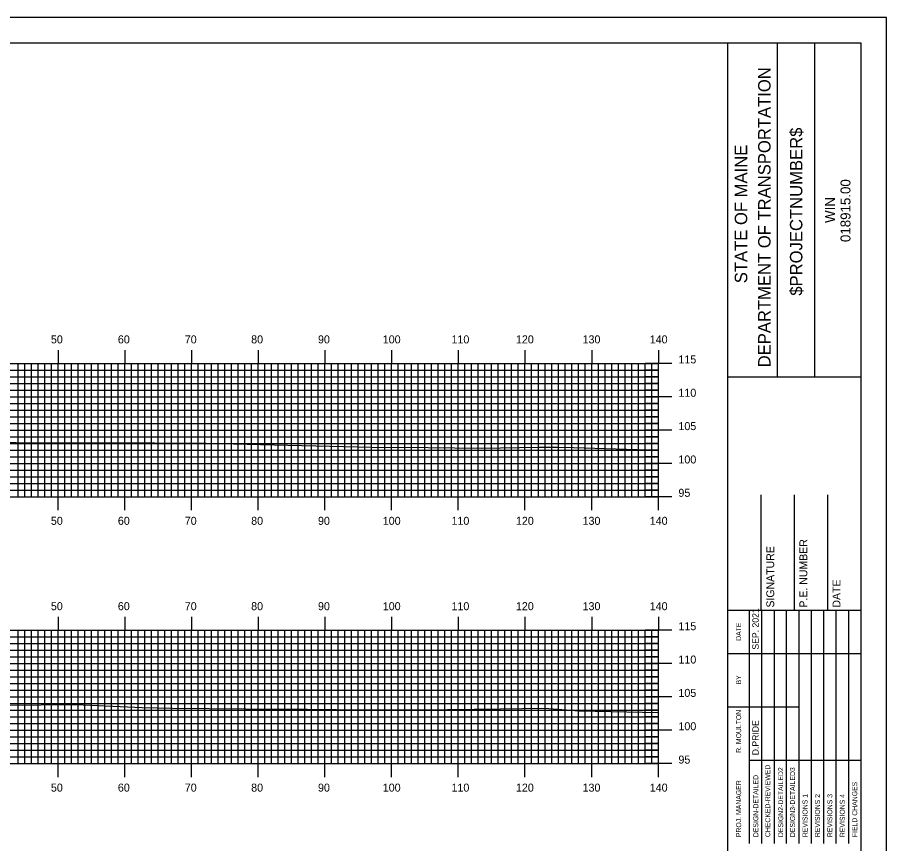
# Model space of a CAD drawing. Extents: x 1773596 to 1773940, y 442591 to 442811.
# Drawn here: x 1773806.1 to 1773936.4, y 442686.7 to 442810.5 of the extents above; entities that cross this region are included whole.
import ezdxf

# ---------------------------------------------------------------- set-up
doc = ezdxf.new("R2010")
doc.units = 0
for name, color, linetype in [('BORDER', 7, 'Continuous'), ('H_V ANNOTATION', 7, 'Continuous'), ('MAJOR', 7, 'Continuous'), ('MINOR', 7, 'Continuous'), ('PLOT BOUNDARY', 7, 'Continuous'), ('S_Roadway_Centerline', 7, 'Continuous')]:
    doc.layers.add(name, color=color, linetype=linetype)

msp = doc.modelspace()

# ---------------------------------------------------------------- linework, layer by layer
at = {"layer": 'BORDER'}
for p, q in [((1773912.55, 442596.67), (1773912.55, 442806.67)), ((1773920, 442756.66), (1773920, 442806.66)), ((1773925.59, 442756.66), (1773925.59, 442806.66)), ((1773912.55, 442756.65), (1773932.55, 442756.65)), ((1773917.55, 442721.67), (1773917.55, 442738.97)), ((1773922.55, 442721.67), (1773922.55, 442738.97)), ((1773927.55, 442721.67), (1773927.55, 442738.97)), ((1773912.55, 442721.67), (1773932.55, 442721.67))]:
    msp.add_line(p, q, dxfattribs=at)
msp.add_lwpolyline([(1773612.55, 442596.67), (1773932.55, 442596.67), (1773932.55, 442806.67), (1773612.55, 442806.67)], close=True, dxfattribs=at)
for points in [[(1773915.78, 442715.17), (1773915.78, 442721.67)], [(1773917.64, 442686.68), (1773917.64, 442721.67)], [(1773919.5, 442721.67), (1773919.5, 442686.68)], [(1773921.37, 442686.68), (1773921.37, 442721.67)], [(1773923.23, 442686.68), (1773923.23, 442721.67)], [(1773925.09, 442686.68), (1773925.09, 442721.67)], [(1773926.96, 442686.68), (1773926.96, 442721.67)], [(1773928.82, 442686.68), (1773928.82, 442721.67)], [(1773930.68, 442686.68), (1773930.68, 442721.67)], [(1773915.78, 442686.68), (1773915.78, 442720.26)], [(1773912.55, 442715.17), (1773932.55, 442715.17)], [(1773912.55, 442707.17), (1773915.78, 442707.17)], [(1773915.78, 442707.17), (1773923.23, 442707.17)], [(1773915.78, 442699.17), (1773932.55, 442699.17)]]:
    msp.add_lwpolyline(points, dxfattribs=at)
at = {"layer": 'MAJOR'}
for p, q in [((1773812.15, 442760.67), (1773812.15, 442758.67)), ((1773822.15, 442760.67), (1773822.15, 442758.67)), ((1773832.15, 442760.67), (1773832.15, 442758.67)), ((1773842.15, 442760.67), (1773842.15, 442758.67)), ((1773852.15, 442760.67), (1773852.15, 442758.67)), ((1773862.15, 442760.67), (1773862.15, 442758.67)), ((1773872.15, 442760.67), (1773872.15, 442758.67)), ((1773882.15, 442760.67), (1773882.15, 442758.67)), ((1773892.15, 442760.67), (1773892.15, 442758.67)), ((1773902.15, 442760.67), (1773902.15, 442758.67)), ((1773622.15, 442758.67), (1773902.15, 442758.67)), ((1773622.15, 442758.67), (1773902.15, 442758.67)), ((1773812.15, 442738.67), (1773812.15, 442758.67)), ((1773822.15, 442738.67), (1773822.15, 442758.67)), ((1773832.15, 442738.67), (1773832.15, 442758.67)), ((1773842.15, 442738.67), (1773842.15, 442758.67)), ((1773852.15, 442738.67), (1773852.15, 442758.67)), ((1773862.15, 442738.67), (1773862.15, 442758.67)), ((1773872.15, 442738.67), (1773872.15, 442758.67)), ((1773882.15, 442738.67), (1773882.15, 442758.67)), ((1773892.15, 442738.67), (1773892.15, 442758.67)), ((1773904.15, 442758.67), (1773900.14, 442758.67)), ((1773902.15, 442738.67), (1773902.15, 442758.67)), ((1773902.15, 442738.67), (1773902.15, 442758.67)), ((1773622.15, 442753.67), (1773902.15, 442753.67)), ((1773904.15, 442753.67), (1773900.14, 442753.67)), ((1773622.15, 442748.67), (1773902.15, 442748.67)), ((1773904.15, 442748.67), (1773900.14, 442748.67)), ((1773622.15, 442743.67), (1773902.15, 442743.67)), ((1773904.15, 442743.67), (1773900.14, 442743.67)), ((1773622.15, 442738.67), (1773902.15, 442738.67)), ((1773622.15, 442738.67), (1773902.15, 442738.67)), ((1773812.15, 442736.66), (1773812.15, 442738.67)), ((1773822.15, 442736.66), (1773822.15, 442738.67)), ((1773832.15, 442736.66), (1773832.15, 442738.67)), ((1773842.15, 442736.66), (1773842.15, 442738.67)), ((1773852.15, 442736.66), (1773852.15, 442738.67)), ((1773862.15, 442736.66), (1773862.15, 442738.67)), ((1773872.15, 442736.66), (1773872.15, 442738.67)), ((1773882.15, 442736.66), (1773882.15, 442738.67)), ((1773892.15, 442736.66), (1773892.15, 442738.67)), ((1773904.15, 442738.67), (1773900.14, 442738.67)), ((1773902.15, 442736.66), (1773902.15, 442738.67)), ((1773812.15, 442720.67), (1773812.15, 442718.67)), ((1773822.15, 442720.67), (1773822.15, 442718.67)), ((1773832.15, 442720.67), (1773832.15, 442718.67)), ((1773842.15, 442720.67), (1773842.15, 442718.67)), ((1773852.15, 442720.67), (1773852.15, 442718.67)), ((1773862.15, 442720.67), (1773862.15, 442718.67)), ((1773872.15, 442720.67), (1773872.15, 442718.67)), ((1773882.15, 442720.67), (1773882.15, 442718.67)), ((1773892.15, 442720.67), (1773892.15, 442718.67)), ((1773902.15, 442720.67), (1773902.15, 442718.67)), ((1773622.15, 442718.67), (1773902.15, 442718.67)), ((1773622.15, 442718.67), (1773902.15, 442718.67)), ((1773812.15, 442698.67), (1773812.15, 442718.67)), ((1773822.15, 442698.67), (1773822.15, 442718.67)), ((1773832.15, 442698.67), (1773832.15, 442718.67)), ((1773842.15, 442698.67), (1773842.15, 442718.67)), ((1773852.15, 442698.67), (1773852.15, 442718.67)), ((1773862.15, 442698.67), (1773862.15, 442718.67)), ((1773872.15, 442698.67), (1773872.15, 442718.67)), ((1773882.15, 442698.67), (1773882.15, 442718.67)), ((1773892.15, 442698.67), (1773892.15, 442718.67)), ((1773904.15, 442718.67), (1773900.14, 442718.67)), ((1773902.15, 442698.67), (1773902.15, 442718.67)), ((1773902.15, 442698.67), (1773902.15, 442718.67)), ((1773622.15, 442713.67), (1773902.15, 442713.67)), ((1773904.15, 442713.67), (1773900.14, 442713.67)), ((1773622.15, 442708.67), (1773902.15, 442708.67)), ((1773904.15, 442708.67), (1773900.14, 442708.67)), ((1773622.15, 442703.67), (1773902.15, 442703.67)), ((1773904.15, 442703.67), (1773900.14, 442703.67)), ((1773622.15, 442698.67), (1773902.15, 442698.67)), ((1773622.15, 442698.67), (1773902.15, 442698.67)), ((1773812.15, 442696.66), (1773812.15, 442698.67)), ((1773822.15, 442696.66), (1773822.15, 442698.67)), ((1773832.15, 442696.66), (1773832.15, 442698.67)), ((1773842.15, 442696.66), (1773842.15, 442698.67)), ((1773852.15, 442696.66), (1773852.15, 442698.67)), ((1773862.15, 442696.66), (1773862.15, 442698.67)), ((1773872.15, 442696.66), (1773872.15, 442698.67)), ((1773882.15, 442696.66), (1773882.15, 442698.67)), ((1773892.15, 442696.66), (1773892.15, 442698.67)), ((1773904.15, 442698.67), (1773900.14, 442698.67)), ((1773902.15, 442696.66), (1773902.15, 442698.67))]:
    msp.add_line(p, q, dxfattribs=at)
at = {"layer": 'MINOR'}
for p, q in [((1773806.15, 442738.67), (1773806.15, 442758.67)), ((1773807.15, 442738.67), (1773807.15, 442758.67)), ((1773808.15, 442738.67), (1773808.15, 442758.67)), ((1773809.15, 442738.67), (1773809.15, 442758.67)), ((1773810.15, 442738.67), (1773810.15, 442758.67)), ((1773811.15, 442738.67), (1773811.15, 442758.67)), ((1773813.15, 442738.67), (1773813.15, 442758.67)), ((1773814.15, 442738.67), (1773814.15, 442758.67)), ((1773815.15, 442738.67), (1773815.15, 442758.67)), ((1773816.15, 442738.67), (1773816.15, 442758.67)), ((1773817.15, 442738.67), (1773817.15, 442758.67)), ((1773818.15, 442738.67), (1773818.15, 442758.67)), ((1773819.15, 442738.67), (1773819.15, 442758.67)), ((1773820.15, 442738.67), (1773820.15, 442758.67)), ((1773821.15, 442738.67), (1773821.15, 442758.67)), ((1773823.15, 442738.67), (1773823.15, 442758.67)), ((1773824.15, 442738.67), (1773824.15, 442758.67)), ((1773825.15, 442738.67), (1773825.15, 442758.67)), ((1773826.15, 442738.67), (1773826.15, 442758.67)), ((1773827.15, 442738.67), (1773827.15, 442758.67)), ((1773828.15, 442738.67), (1773828.15, 442758.67)), ((1773829.15, 442738.67), (1773829.15, 442758.67)), ((1773830.15, 442738.67), (1773830.15, 442758.67)), ((1773831.15, 442738.67), (1773831.15, 442758.67)), ((1773833.15, 442738.67), (1773833.15, 442758.67)), ((1773834.15, 442738.67), (1773834.15, 442758.67)), ((1773835.15, 442738.67), (1773835.15, 442758.67)), ((1773836.15, 442738.67), (1773836.15, 442758.67)), ((1773837.15, 442738.67), (1773837.15, 442758.67)), ((1773838.15, 442738.67), (1773838.15, 442758.67)), ((1773839.15, 442738.67), (1773839.15, 442758.67)), ((1773840.15, 442738.67), (1773840.15, 442758.67)), ((1773841.15, 442738.67), (1773841.15, 442758.67)), ((1773843.15, 442738.67), (1773843.15, 442758.67)), ((1773844.15, 442738.67), (1773844.15, 442758.67)), ((1773845.15, 442738.67), (1773845.15, 442758.67)), ((1773846.15, 442738.67), (1773846.15, 442758.67)), ((1773847.15, 442738.67), (1773847.15, 442758.67)), ((1773848.15, 442738.67), (1773848.15, 442758.67)), ((1773849.15, 442738.67), (1773849.15, 442758.67)), ((1773850.15, 442738.67), (1773850.15, 442758.67)), ((1773851.15, 442738.67), (1773851.15, 442758.67)), ((1773853.15, 442738.67), (1773853.15, 442758.67)), ((1773854.15, 442738.67), (1773854.15, 442758.67)), ((1773855.15, 442738.67), (1773855.15, 442758.67)), ((1773856.15, 442738.67), (1773856.15, 442758.67)), ((1773857.15, 442738.67), (1773857.15, 442758.67)), ((1773858.15, 442738.67), (1773858.15, 442758.67)), ((1773859.15, 442738.67), (1773859.15, 442758.67)), ((1773860.15, 442738.67), (1773860.15, 442758.67)), ((1773861.15, 442738.67), (1773861.15, 442758.67)), ((1773863.15, 442738.67), (1773863.15, 442758.67)), ((1773864.15, 442738.67), (1773864.15, 442758.67)), ((1773865.15, 442738.67), (1773865.15, 442758.67)), ((1773866.15, 442738.67), (1773866.15, 442758.67)), ((1773867.15, 442738.67), (1773867.15, 442758.67)), ((1773868.15, 442738.67), (1773868.15, 442758.67)), ((1773869.15, 442738.67), (1773869.15, 442758.67)), ((1773870.15, 442738.67), (1773870.15, 442758.67)), ((1773871.15, 442738.67), (1773871.15, 442758.67)), ((1773873.15, 442738.67), (1773873.15, 442758.67)), ((1773874.15, 442738.67), (1773874.15, 442758.67)), ((1773875.15, 442738.67), (1773875.15, 442758.67)), ((1773876.15, 442738.67), (1773876.15, 442758.67)), ((1773877.15, 442738.67), (1773877.15, 442758.67)), ((1773878.15, 442738.67), (1773878.15, 442758.67)), ((1773879.15, 442738.67), (1773879.15, 442758.67)), ((1773880.15, 442738.67), (1773880.15, 442758.67)), ((1773881.15, 442738.67), (1773881.15, 442758.67)), ((1773883.15, 442738.67), (1773883.15, 442758.67)), ((1773884.15, 442738.67), (1773884.15, 442758.67)), ((1773885.15, 442738.67), (1773885.15, 442758.67)), ((1773886.15, 442738.67), (1773886.15, 442758.67)), ((1773887.15, 442738.67), (1773887.15, 442758.67)), ((1773888.15, 442738.67), (1773888.15, 442758.67)), ((1773889.15, 442738.67), (1773889.15, 442758.67)), ((1773890.15, 442738.67), (1773890.15, 442758.67)), ((1773891.15, 442738.67), (1773891.15, 442758.67)), ((1773893.15, 442738.67), (1773893.15, 442758.67)), ((1773894.15, 442738.67), (1773894.15, 442758.67)), ((1773895.15, 442738.67), (1773895.15, 442758.67)), ((1773896.15, 442738.67), (1773896.15, 442758.67)), ((1773897.15, 442738.67), (1773897.15, 442758.67)), ((1773898.15, 442738.67), (1773898.15, 442758.67)), ((1773899.15, 442738.67), (1773899.15, 442758.67)), ((1773900.15, 442738.67), (1773900.15, 442758.67)), ((1773901.15, 442738.67), (1773901.15, 442758.67)), ((1773622.15, 442757.67), (1773902.15, 442757.67)), ((1773902.15, 442757.67), (1773900.14, 442757.67)), ((1773622.15, 442756.67), (1773902.15, 442756.67)), ((1773622.15, 442755.67), (1773902.15, 442755.67)), ((1773902.15, 442756.67), (1773900.14, 442756.67)), ((1773902.15, 442755.67), (1773900.14, 442755.67)), ((1773622.15, 442754.67), (1773902.15, 442754.67)), ((1773902.15, 442754.67), (1773900.14, 442754.67)), ((1773622.15, 442752.67), (1773902.15, 442752.67)), ((1773902.15, 442752.67), (1773900.14, 442752.67)), ((1773622.15, 442751.67), (1773902.15, 442751.67)), ((1773622.15, 442750.67), (1773902.15, 442750.67)), ((1773902.15, 442751.67), (1773900.14, 442751.67)), ((1773902.15, 442750.67), (1773900.14, 442750.67)), ((1773622.15, 442749.67), (1773902.15, 442749.67)), ((1773902.15, 442749.67), (1773900.14, 442749.67)), ((1773622.15, 442747.67), (1773902.15, 442747.67)), ((1773622.15, 442746.67), (1773902.15, 442746.67)), ((1773902.15, 442747.67), (1773900.14, 442747.67)), ((1773902.15, 442746.67), (1773900.14, 442746.67)), ((1773622.15, 442745.67), (1773902.15, 442745.67)), ((1773902.15, 442745.67), (1773900.14, 442745.67)), ((1773622.15, 442744.67), (1773902.15, 442744.67)), ((1773902.15, 442744.67), (1773900.14, 442744.67)), ((1773622.15, 442742.67), (1773902.15, 442742.67)), ((1773902.15, 442742.67), (1773900.14, 442742.67)), ((1773622.15, 442741.67), (1773902.15, 442741.67)), ((1773902.15, 442741.67), (1773900.14, 442741.67)), ((1773622.15, 442740.67), (1773902.15, 442740.67)), ((1773902.15, 442740.67), (1773900.14, 442740.67)), ((1773622.15, 442739.67), (1773902.15, 442739.67)), ((1773902.15, 442739.67), (1773900.14, 442739.67)), ((1773806.15, 442698.67), (1773806.15, 442718.67)), ((1773807.15, 442698.67), (1773807.15, 442718.67)), ((1773808.15, 442698.67), (1773808.15, 442718.67)), ((1773809.15, 442698.67), (1773809.15, 442718.67)), ((1773810.15, 442698.67), (1773810.15, 442718.67)), ((1773811.15, 442698.67), (1773811.15, 442718.67)), ((1773813.15, 442698.67), (1773813.15, 442718.67)), ((1773814.15, 442698.67), (1773814.15, 442718.67)), ((1773815.15, 442698.67), (1773815.15, 442718.67)), ((1773816.15, 442698.67), (1773816.15, 442718.67)), ((1773817.15, 442698.67), (1773817.15, 442718.67)), ((1773818.15, 442698.67), (1773818.15, 442718.67)), ((1773819.15, 442698.67), (1773819.15, 442718.67)), ((1773820.15, 442698.67), (1773820.15, 442718.67)), ((1773821.15, 442698.67), (1773821.15, 442718.67)), ((1773823.15, 442698.67), (1773823.15, 442718.67)), ((1773824.15, 442698.67), (1773824.15, 442718.67)), ((1773825.15, 442698.67), (1773825.15, 442718.67)), ((1773826.15, 442698.67), (1773826.15, 442718.67)), ((1773827.15, 442698.67), (1773827.15, 442718.67)), ((1773828.15, 442698.67), (1773828.15, 442718.67)), ((1773829.15, 442698.67), (1773829.15, 442718.67)), ((1773830.15, 442698.67), (1773830.15, 442718.67)), ((1773831.15, 442698.67), (1773831.15, 442718.67)), ((1773833.15, 442698.67), (1773833.15, 442718.67)), ((1773834.15, 442698.67), (1773834.15, 442718.67)), ((1773835.15, 442698.67), (1773835.15, 442718.67)), ((1773836.15, 442698.67), (1773836.15, 442718.67)), ((1773837.15, 442698.67), (1773837.15, 442718.67)), ((1773838.15, 442698.67), (1773838.15, 442718.67)), ((1773839.15, 442698.67), (1773839.15, 442718.67)), ((1773840.15, 442698.67), (1773840.15, 442718.67)), ((1773841.15, 442698.67), (1773841.15, 442718.67)), ((1773843.15, 442698.67), (1773843.15, 442718.67)), ((1773844.15, 442698.67), (1773844.15, 442718.67)), ((1773845.15, 442698.67), (1773845.15, 442718.67)), ((1773846.15, 442698.67), (1773846.15, 442718.67)), ((1773847.15, 442698.67), (1773847.15, 442718.67)), ((1773848.15, 442698.67), (1773848.15, 442718.67)), ((1773849.15, 442698.67), (1773849.15, 442718.67)), ((1773850.15, 442698.67), (1773850.15, 442718.67)), ((1773851.15, 442698.67), (1773851.15, 442718.67)), ((1773853.15, 442698.67), (1773853.15, 442718.67)), ((1773854.15, 442698.67), (1773854.15, 442718.67)), ((1773855.15, 442698.67), (1773855.15, 442718.67)), ((1773856.15, 442698.67), (1773856.15, 442718.67)), ((1773857.15, 442698.67), (1773857.15, 442718.67)), ((1773858.15, 442698.67), (1773858.15, 442718.67)), ((1773859.15, 442698.67), (1773859.15, 442718.67)), ((1773860.15, 442698.67), (1773860.15, 442718.67)), ((1773861.15, 442698.67), (1773861.15, 442718.67)), ((1773863.15, 442698.67), (1773863.15, 442718.67)), ((1773864.15, 442698.67), (1773864.15, 442718.67)), ((1773865.15, 442698.67), (1773865.15, 442718.67)), ((1773866.15, 442698.67), (1773866.15, 442718.67)), ((1773867.15, 442698.67), (1773867.15, 442718.67)), ((1773868.15, 442698.67), (1773868.15, 442718.67)), ((1773869.15, 442698.67), (1773869.15, 442718.67)), ((1773870.15, 442698.67), (1773870.15, 442718.67)), ((1773871.15, 442698.67), (1773871.15, 442718.67)), ((1773873.15, 442698.67), (1773873.15, 442718.67)), ((1773874.15, 442698.67), (1773874.15, 442718.67)), ((1773875.15, 442698.67), (1773875.15, 442718.67)), ((1773876.15, 442698.67), (1773876.15, 442718.67)), ((1773877.15, 442698.67), (1773877.15, 442718.67)), ((1773878.15, 442698.67), (1773878.15, 442718.67)), ((1773879.15, 442698.67), (1773879.15, 442718.67)), ((1773880.15, 442698.67), (1773880.15, 442718.67)), ((1773881.15, 442698.67), (1773881.15, 442718.67)), ((1773883.15, 442698.67), (1773883.15, 442718.67)), ((1773884.15, 442698.67), (1773884.15, 442718.67)), ((1773885.15, 442698.67), (1773885.15, 442718.67)), ((1773886.15, 442698.67), (1773886.15, 442718.67)), ((1773887.15, 442698.67), (1773887.15, 442718.67)), ((1773888.15, 442698.67), (1773888.15, 442718.67)), ((1773889.15, 442698.67), (1773889.15, 442718.67)), ((1773890.15, 442698.67), (1773890.15, 442718.67)), ((1773891.15, 442698.67), (1773891.15, 442718.67)), ((1773893.15, 442698.67), (1773893.15, 442718.67)), ((1773894.15, 442698.67), (1773894.15, 442718.67)), ((1773895.15, 442698.67), (1773895.15, 442718.67)), ((1773896.15, 442698.67), (1773896.15, 442718.67)), ((1773897.15, 442698.67), (1773897.15, 442718.67)), ((1773898.15, 442698.67), (1773898.15, 442718.67)), ((1773899.15, 442698.67), (1773899.15, 442718.67)), ((1773900.15, 442698.67), (1773900.15, 442718.67)), ((1773901.15, 442698.67), (1773901.15, 442718.67)), ((1773622.15, 442717.67), (1773902.15, 442717.67)), ((1773622.15, 442716.67), (1773902.15, 442716.67)), ((1773902.15, 442717.67), (1773900.14, 442717.67)), ((1773902.15, 442716.67), (1773900.14, 442716.67)), ((1773622.15, 442715.67), (1773902.15, 442715.67)), ((1773902.15, 442715.67), (1773900.14, 442715.67)), ((1773622.15, 442714.67), (1773902.15, 442714.67)), ((1773902.15, 442714.67), (1773900.14, 442714.67)), ((1773622.15, 442712.67), (1773902.15, 442712.67)), ((1773902.15, 442712.67), (1773900.14, 442712.67)), ((1773622.15, 442711.67), (1773902.15, 442711.67)), ((1773902.15, 442711.67), (1773900.14, 442711.67)), ((1773622.15, 442710.67), (1773902.15, 442710.67)), ((1773902.15, 442710.67), (1773900.14, 442710.67)), ((1773622.15, 442709.67), (1773902.15, 442709.67)), ((1773902.15, 442709.67), (1773900.14, 442709.67)), ((1773622.15, 442707.67), (1773902.15, 442707.67)), ((1773902.15, 442707.67), (1773900.14, 442707.67)), ((1773622.15, 442706.67), (1773902.15, 442706.67)), ((1773902.15, 442706.67), (1773900.14, 442706.67)), ((1773622.15, 442705.67), (1773902.15, 442705.67)), ((1773902.15, 442705.67), (1773900.14, 442705.67)), ((1773622.15, 442704.67), (1773902.15, 442704.67)), ((1773902.15, 442704.67), (1773900.14, 442704.67)), ((1773622.15, 442702.67), (1773902.15, 442702.67)), ((1773902.15, 442702.67), (1773900.14, 442702.67)), ((1773622.15, 442701.67), (1773902.15, 442701.67)), ((1773902.15, 442701.67), (1773900.14, 442701.67)), ((1773622.15, 442700.67), (1773902.15, 442700.67)), ((1773622.15, 442699.67), (1773902.15, 442699.67)), ((1773902.15, 442700.67), (1773900.14, 442700.67)), ((1773902.15, 442699.67), (1773900.14, 442699.67))]:
    msp.add_line(p, q, dxfattribs=at)
at = {"layer": 'PLOT BOUNDARY'}
msp.add_lwpolyline([(1773596.36, 442590.55), (1773936.36, 442590.55), (1773936.36, 442810.55), (1773596.36, 442810.55)], close=True, dxfattribs=at)
at = {"layer": 'S_Roadway_Centerline'}
for points in [[(1773801.39, 442746.84), (1773810.38, 442746.78), (1773824.14, 442746.8), (1773829.05, 442746.71), (1773834.34, 442746.7), (1773846.58, 442746.39), (1773859.12, 442746.11), (1773867.64, 442746.07), (1773875.59, 442745.97), (1773884.23, 442746.11), (1773886.97, 442746.12), (1773889.43, 442746.04), (1773902.15, 442745.65)], [(1773804.38, 442707.42), (1773814.8, 442707.54), (1773824.78, 442707.1), (1773827.02, 442707.03), (1773829.31, 442706.99), (1773845.81, 442706.81), (1773849.5, 442706.84), (1773853.91, 442706.78), (1773866.58, 442706.73), (1773878.48, 442706.9), (1773885.05, 442706.96), (1773890.28, 442706.6), (1773902.15, 442706.35)]]:
    msp.add_lwpolyline(points, dxfattribs=at)

# ---------------------------------------------------------------- texts
at = {"layer": 'BORDER'}
for s, height, p in [('DEPARTMENT OF TRANSPORTATION', 1.8635, (1773918.96, 442758.08)), ('$PROJECTNUMBER$', 1.8635, (1773923.73, 442768.82)), ('STATE OF MAINE', 1.8635, (1773915.46, 442770.69)), ('018915.00', 1.491, (1773930.94, 442776.86)), ('WIN', 1.491, (1773928.62, 442779.73)), ('P.E. NUMBER', 1.1811, (1773924.47, 442722.06)), ('SIGNATURE', 1.181, (1773919.51, 442722.06)), ('DATE', 1.181, (1773929.43, 442722.06)), ('SEP. 2021', 0.969, (1773917.19, 442715.76)), ('DATE', 0.743, (1773914.55, 442717.08)), ('BY', 0.743, (1773914.55, 442710.54)), ('R. MOULTON', 0.745, (1773914.55, 442700.28)), ('D.PRIDE', 0.969, (1773917.19, 442699.92)), ('CHECKED-REVIEWED', 0.7455, (1773918.91, 442687.65)), ('DESIGN2-DETAILED2', 0.7455, (1773920.85, 442687.65)), ('DESIGN3-DETAILED3', 0.7455, (1773922.63, 442687.65)), ('PROJ. MANAGER', 0.7455, (1773914.55, 442687.65)), ('DESIGN-DETAILED', 0.7455, (1773917.12, 442687.65)), ('FIELD CHANGES', 0.7455, (1773931.95, 442687.65)), ('REVISIONS 1', 0.7455, (1773924.5, 442687.65)), ('REVISIONS 2', 0.7455, (1773926.36, 442687.65)), ('REVISIONS 3', 0.7455, (1773928.22, 442687.65)), ('REVISIONS 4', 0.7455, (1773930.09, 442687.65))]:
    msp.add_text(s, height=height, rotation=90, dxfattribs=at).set_placement(p)
at = {"layer": 'H_V ANNOTATION'}
for s, p in [('50', (1773811.08, 442761.67)), ('60', (1773821.12, 442761.67)), ('70', (1773831.15, 442761.67)), ('80', (1773841.1, 442761.67)), ('90', (1773851.12, 442761.67)), ('100', (1773860.83, 442761.67)), ('110', (1773871.13, 442761.67)), ('120', (1773880.79, 442761.67)), ('130', (1773890.78, 442761.67)), ('140', (1773900.85, 442761.67)), ('115', (1773905.15, 442758.67)), ('110', (1773905.15, 442753.67)), ('105', (1773905.15, 442748.67)), ('100', (1773905.15, 442743.67)), ('95', (1773905.15, 442738.67)), ('50', (1773811.08, 442734.47)), ('60', (1773821.12, 442734.47)), ('70', (1773831.15, 442734.47)), ('80', (1773841.1, 442734.47)), ('90', (1773851.12, 442734.47)), ('100', (1773860.83, 442734.47)), ('110', (1773871.13, 442734.47)), ('120', (1773880.79, 442734.47)), ('130', (1773890.78, 442734.47)), ('140', (1773900.85, 442734.47)), ('50', (1773811.08, 442721.67)), ('60', (1773821.12, 442721.67)), ('70', (1773831.15, 442721.67)), ('80', (1773841.1, 442721.67)), ('90', (1773851.12, 442721.67)), ('100', (1773860.83, 442721.67)), ('110', (1773871.13, 442721.67)), ('120', (1773880.79, 442721.67)), ('130', (1773890.78, 442721.67)), ('140', (1773900.85, 442721.67)), ('115', (1773905.15, 442718.67)), ('110', (1773905.15, 442713.67)), ('105', (1773905.15, 442708.67)), ('100', (1773905.15, 442703.67)), ('95', (1773905.15, 442698.67)), ('50', (1773811.08, 442694.47)), ('60', (1773821.12, 442694.47)), ('70', (1773831.15, 442694.47)), ('80', (1773841.1, 442694.47)), ('90', (1773851.12, 442694.47)), ('100', (1773860.83, 442694.47)), ('110', (1773871.13, 442694.47)), ('120', (1773880.79, 442694.47)), ('130', (1773890.78, 442694.47)), ('140', (1773900.85, 442694.47))]:
    msp.add_text(s, height=1.2, dxfattribs=at).set_placement(p)

doc.saveas('drawing.dxf')
